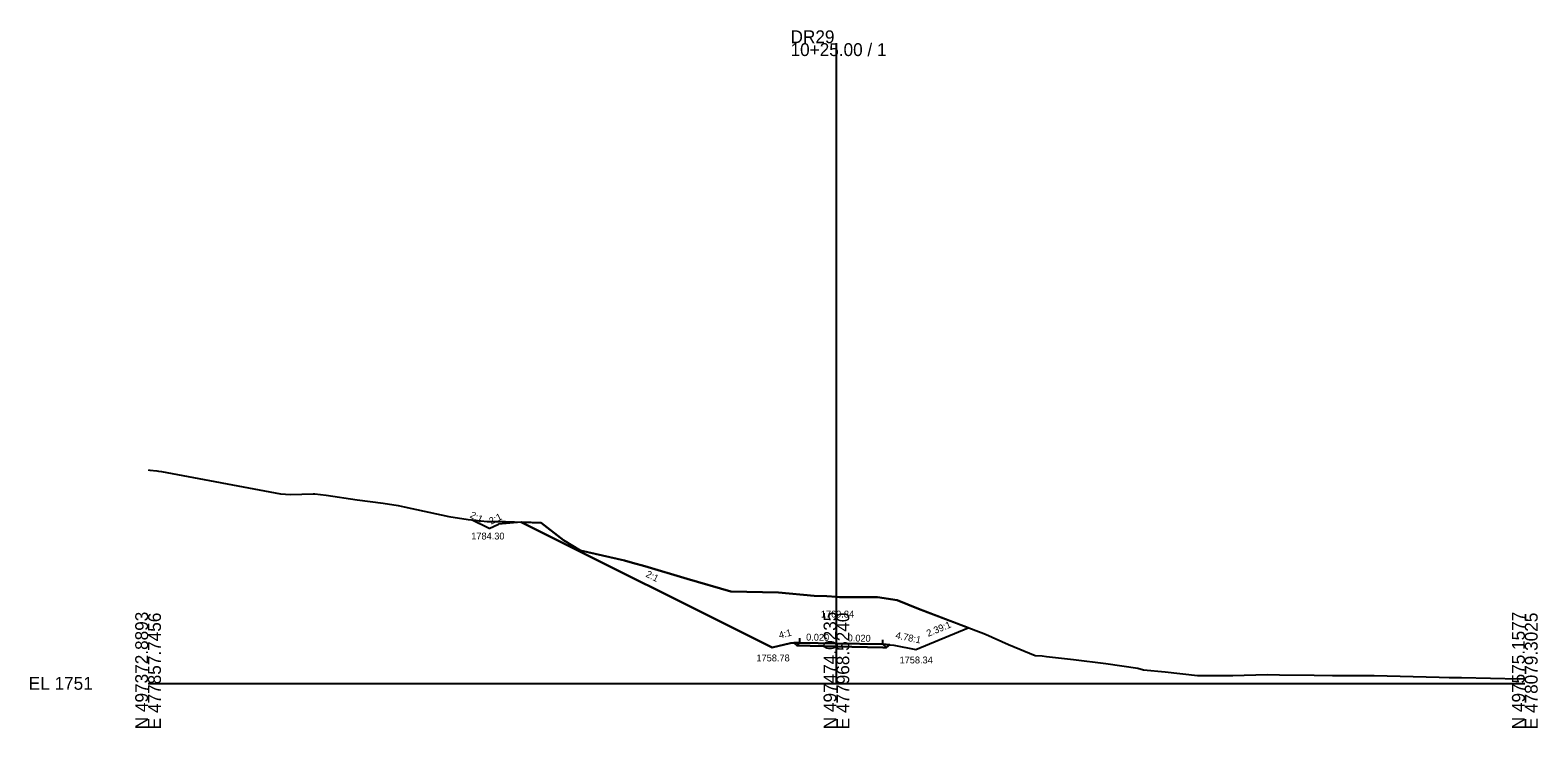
# Model space of a CAD drawing. Extents: x -26 to 303, y -10 to 4734.
# Drawn here: x -25.7 to 302.8, y 490.3 to 642.3 of the extents above; entities that cross this region are included whole.
import ezdxf

# ---------------------------------------------------------------- set-up
doc = ezdxf.new("R2010")
doc.units = 0
for name, color, linetype in [('Exist Cross Section Cell', 7, 'Continuous'), ('Exist XS Center Line Elevation Label', 7, 'Continuous'), ('Exist XS Ground Line', 7, 'Continuous'), ('Prop XS DDE', 7, 'Continuous'), ('Prop XS DDE Elevations', 7, 'Continuous'), ('Prop XS DDE Slope Text', 7, 'Continuous'), ('Prop XS Ditch Slope Text', 7, 'Continuous'), ('Prop XS Ditch Standard Text', 7, 'Continuous'), ('Prop XS Dump Level', 7, 'Continuous'), ('Prop XS Earthwork Shape', 7, 'Continuous'), ('Prop XS EOT Tick Mark', 7, 'Continuous'), ('Prop XS Finish Grade', 7, 'Continuous'), ('Prop XS Finish Grade Earthwork', 7, 'Continuous'), ('Prop XS Finish Grade Pavement', 7, 'Continuous'), ('Prop XS Pvmt Edge Slope', 7, 'Continuous'), ('Prop XS SE Text', 7, 'Continuous'), ('Prop XS Shoulder Borrow Shape', 7, 'Continuous'), ('Prop XS Side Slope Text', 7, 'Continuous'), ('Prop XS Subgrade Earthwork', 7, 'Continuous')]:
    doc.layers.add(name, color=color, linetype=linetype)

msp = doc.modelspace()

# ---------------------------------------------------------------- linework, layer by layer
at = {"layer": 'Exist Cross Section Cell'}
for p, q in [((150, 500), (150, 639.46)), ((0, 500), (150, 500)), ((150, 500), (300, 500))]:
    msp.add_line(p, q, dxfattribs=at)
at = {"layer": 'Exist XS Ground Line'}
msp.add_lwpolyline([(0, 546.49), (0.42, 546.42), (1.89, 546.27), (2.28, 546.23), (2.91, 546.16), (28.85, 541.3), (31.02, 541.15), (35.96, 541.31), (36.31, 541.28), (38.8, 540.97), (45.53, 539.97), (51.22, 539.22), (54.47, 538.72), (55.83, 538.46), (65.51, 536.34), (69.75, 535.71), (73.9, 535.26), (77.92, 535.26), (85.64, 534.96), (90.51, 531.21), (94.22, 528.97), (103.79, 526.73), (105.56, 526.27), (108.26, 525.52), (117.49, 522.78), (126.96, 520.04), (137.35, 519.76), (145.16, 519.08), (147.89, 518.99), (150, 518.84), (150.68, 518.79), (158.94, 518.75), (163.25, 518.12), (167.88, 516.2), (181.53, 511.07), (182.46, 510.68), (187.46, 508.49), (193.28, 506.1), (194.83, 505.96), (195.79, 505.84), (201.65, 505.21), (208.71, 504.34), (215.7, 503.28), (216.92, 502.96), (221.64, 502.53), (228.66, 501.72), (229.62, 501.7), (236.36, 501.71), (243.87, 501.9), (246.52, 501.87), (254.12, 501.77), (258.11, 501.69), (259.94, 501.71), (267.18, 501.72), (281.35, 501.34), (283.54, 501.29), (286.23, 501.25), (298.86, 501.01), (300, 501.06)], dxfattribs=at)
at = {"layer": 'Prop XS DDE'}
for p, q in [((74.33, 533.71), (70.5, 535.63)), ((74.33, 533.71), (76.33, 534.71)), ((81.31, 535.13), (76.33, 534.71))]:
    msp.add_line(p, q, dxfattribs=at)
at = {"layer": 'Prop XS Dump Level'}
for p, q in [((150, 508.7), (142, 508.86)), ((160.11, 508.5), (150, 508.7))]:
    msp.add_line(p, q, dxfattribs=at)
at = {"layer": 'Prop XS Earthwork Shape'}
msp.add_lwpolyline([(160.92, 507.82), (161.61, 508.4), (162.5, 508.34), (167.28, 507.34), (178.72, 512.13), (167.88, 516.2), (163.25, 518.12), (158.94, 518.75), (150.68, 518.79), (150, 518.84), (147.89, 518.99), (145.16, 519.08), (137.35, 519.76), (126.96, 520.04), (117.49, 522.78), (108.26, 525.52), (105.56, 526.27), (103.79, 526.73), (94.22, 528.97), (90.51, 531.21), (85.64, 534.96), (81.31, 535.13), (136, 507.78), (140, 508.78), (140.74, 508.81), (141.35, 508.21), (150, 508), (160.11, 507.83)], close=True, dxfattribs=at)
at = {"layer": 'Prop XS EOT Tick Mark'}
for p, q in [((142, 508.86), (142, 509.86)), ((160.11, 508.5), (160.11, 509.5))]:
    msp.add_line(p, q, dxfattribs=at)
at = {"layer": 'Prop XS Finish Grade'}
for p, q in [((142, 508.86), (140.74, 508.81)), ((160.11, 508.5), (161.61, 508.4))]:
    msp.add_line(p, q, dxfattribs=at)
at = {"layer": 'Prop XS Finish Grade Earthwork'}
for p, q in [((136, 507.78), (81.31, 535.13)), ((167.28, 507.34), (178.72, 512.13)), ((140, 508.78), (136, 507.78)), ((140.74, 508.81), (140, 508.78)), ((161.61, 508.4), (162.5, 508.34)), ((162.5, 508.34), (167.28, 507.34))]:
    msp.add_line(p, q, dxfattribs=at)
at = {"layer": 'Prop XS Finish Grade Pavement'}
for p, q in [((142, 508.86), (150, 508.7)), ((150, 508.7), (160.11, 508.5))]:
    msp.add_line(p, q, dxfattribs=at)
at = {"layer": 'Prop XS Pvmt Edge Slope'}
for p, q in [((142, 508.86), (141.35, 508.21)), ((160.11, 508.5), (160.92, 507.82))]:
    msp.add_line(p, q, dxfattribs=at)
at = {"layer": 'Prop XS Shoulder Borrow Shape'}
for points in [[(142, 508.86), (141.35, 508.21), (140.74, 508.81)], [(160.92, 507.82), (161.61, 508.4), (160.11, 508.5)]]:
    msp.add_lwpolyline(points, close=True, dxfattribs=at)
at = {"layer": 'Prop XS Subgrade Earthwork'}
for p, q in [((141.35, 508.21), (140.74, 508.81)), ((150, 508), (141.35, 508.21)), ((160.11, 507.83), (150, 508)), ((160.11, 507.83), (160.92, 507.82)), ((160.92, 507.82), (161.61, 508.4))]:
    msp.add_line(p, q, dxfattribs=at)

# ---------------------------------------------------------------- texts
at = {"layer": 'Exist Cross Section Cell'}
for s, p in [('DR29', (140, 639.46)), ('10+25.00 / 1', (140, 636.66)), ('EL 1751', (-26, 498.6))]:
    msp.add_text(s, height=2.8, dxfattribs=at).set_placement(p)
for s, p in [('N 497372.8893', (0, 490)), ('E 477857.7456', (2.8, 490)), ('N 497474.0235', (150, 490)), ('E 477968.5240', (152.8, 490)), ('N 497575.1577', (300, 490)), ('E 478079.3025', (302.8, 490))]:
    msp.add_text(s, height=2.8, rotation=90, dxfattribs=at).set_placement(p)
at = {"layer": 'Exist XS Center Line Elevation Label'}
msp.add_text('1769.84', height=1.5, dxfattribs=at).set_placement((146.6, 514.34))
at = {"layer": 'Prop XS DDE Elevations'}
msp.add_text('1784.30', height=1.5, dxfattribs=at).set_placement((70.42, 531.34))
at = {"layer": 'Prop XS DDE Slope Text'}
for rotation, p in [(333.4349, (69.99, 536.2)), (26.5651, (74.77, 534.56))]:
    msp.add_text('2:1', height=1.5, rotation=rotation, dxfattribs=at).set_placement(p)
at = {"layer": 'Prop XS Ditch Slope Text'}
for s, rotation, p in [('4:1', 14.0362, (137.64, 509.74)), ('4.78:1', 348.1857, (162.79, 509.81))]:
    msp.add_text(s, height=1.5, rotation=rotation, dxfattribs=at).set_placement(p)
at = {"layer": 'Prop XS Ditch Standard Text'}
for s, p in [('1758.78', (132.57, 504.78)), ('1758.34', (163.75, 504.34))]:
    msp.add_text(s, height=1.5, dxfattribs=at).set_placement(p)
at = {"layer": 'Prop XS Dump Level'}
for p in [(140, 508.74), (162.5, 508.3)]:
    msp.add_text('Case1', height=0.04, dxfattribs=at).set_placement(p)
at = {"layer": 'Prop XS SE Text'}
for p in [(143.38, 509.34), (152.43, 509.15)]:
    msp.add_text('0.020', height=1.5, rotation=358.8542, dxfattribs=at).set_placement(p)
at = {"layer": 'Prop XS Side Slope Text'}
for s, rotation, p in [('2:1', 333.4349, (108.31, 523.31)), ('2.39:1', 22.7016, (170, 510.11))]:
    msp.add_text(s, height=1.5, rotation=rotation, dxfattribs=at).set_placement(p)

doc.saveas('drawing.dxf')
